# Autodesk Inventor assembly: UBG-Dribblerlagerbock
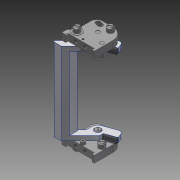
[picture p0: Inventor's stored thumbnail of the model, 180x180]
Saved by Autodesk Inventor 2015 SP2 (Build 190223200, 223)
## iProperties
Created: 2012-07
Part Number: UBG-Dribblerlagerbock
Document SubType Name: Assembly
Designer: rYan
Mass: 50.5394 g
Surface Area: 78.4637 cm^2
Volume: 8.51648 cm^3
Density: 5.9343 g/cm^3
Author: rYan
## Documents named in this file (8)
- D:\TIGERs GIT\Hardware\mechanik\2016\Inventor\Dribbling Device\UBG-Dribblerlagerbock.iam
- D:\TIGERs GIT\Hardware\mechanik\2016\Inventor\Dribbling Device\Chipperstuetze.ipt
- D:\TIGERs GIT\Hardware\mechanik\2016\Inventor\Inhaltscenter\de-DE\DIN 927\DIN 927 - M4 x 4-14H.ipt
- D:\TIGERs GIT\Hardware\mechanik\2016\Inventor\Kicker\Chip\Chipperschwinge.ipt
- D:\TIGERs GIT\Hardware\mechanik\2016\Inventor\Inhaltscenter\de-DE\DIN 988(2)\DIN 988 - 4 x 8 x 0,3.ipt
- D:\TIGERs GIT\Hardware\mechanik\2016\Inventor\Inhaltscenter\de-DE\DIN 927\DIN 927 - M4 x 5-14H.ipt
- D:\TIGERs GIT\Hardware\mechanik\2016\Inventor\Inhaltscenter\de-DE\ISO 4762(1)\ISO 4762 - M2 x 5DIN EN ISO.ipt
- D:\TIGERs GIT\Hardware\mechanik\2016\Inventor\Kaufteile\Gelpad 10x4.ipt
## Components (19 placed, 7 different names)
1. Chipperstütze:1 — Fluchtend:1, Fluchtend:2, Passend:48, Einfügen:2, Einfügen:4, Einfügen:6, Einfügen:8, Einfügen:9
2. Chipperstütze:2 — Fluchtend:1, Fluchtend:2, Passend:49, Winkel:1, Einfügen:1, Einfügen:3, Einfügen:5, Einfügen:7, Einfügen:10
3. DIN 927 M4 x 4-14H:2 — Passend:54
4. DIN 927 M4 x 4-14H:3 — Passend:53
5. DIN 927 M4 x 5-14H:1 — Passend:55
6. DIN 927 M4 x 5-14H:2 — Passend:50, Passend:56
7. Chipperschwinge:1 — Passend:48, Passend:49, Passend:50, Winkel:1, Passend:57, Fluchtend:3, Fluchtend:4, Passend:58, Fluchtend:5, Fluchtend:6
8. DIN 988 4 x 8 x 0,3:1 — Einfügen:1, Passend:53
9. DIN 988 4 x 8 x 0,3:2 — Einfügen:2, Passend:54
10. DIN 988 4 x 8 x 0,3:3 — Einfügen:4, Passend:55
11. DIN 988 4 x 8 x 0,3:4 — Einfügen:3, Passend:56
12. DIN EN ISO 4762 M2 x 5:1 — Einfügen:5
13. DIN EN ISO 4762 M2 x 5:2 — Einfügen:6
14. DIN 927 M4 x 4-14H:4 — Einfügen:7
15. DIN 927 M4 x 4-14H:5 — Einfügen:8
16. DIN 927 M4 x 4-14H:6 — Einfügen:9
17. Gelpad 10x4:1 — Passend:57, Fluchtend:3, Fluchtend:4
18. Gelpad 10x4:2 — Passend:58, Fluchtend:5, Fluchtend:6
19. DIN 927 M4 x 4-14H:7 — Einfügen:10
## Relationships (26: Insert 10, Mate 9, Flush 6, Angle 1)
- Fluchtend:1 [Flush]: Chipperstütze:1 ↔ Chipperstütze:2
- Fluchtend:2 [Flush]: Chipperstütze:1 ↔ Chipperstütze:2
- Passend:48 [Mate]: Chipperstütze:1 ↔ Chipperschwinge:1
- Passend:49 [Mate]: Chipperstütze:2 ↔ Chipperschwinge:1
- Passend:50 [Mate]: DIN 927 M4 x 5-14H:2 ↔ Chipperschwinge:1
- Winkel:1 [Angle]: Chipperstütze:2 ↔ Chipperschwinge:1
- Einfügen:1 [Insert]: Chipperstütze:2 ↔ DIN 988 4 x 8 x 0,3:1
- Passend:53 [Mate]: DIN 927 M4 x 4-14H:3 ↔ DIN 988 4 x 8 x 0,3:1
- Einfügen:2 [Insert]: Chipperstütze:1 ↔ DIN 988 4 x 8 x 0,3:2
- Passend:54 [Mate]: DIN 927 M4 x 4-14H:2 ↔ DIN 988 4 x 8 x 0,3:2
- Einfügen:3 [Insert]: Chipperstütze:2 ↔ DIN 988 4 x 8 x 0,3:4
- Einfügen:4 [Insert]: Chipperstütze:1 ↔ DIN 988 4 x 8 x 0,3:3
- Passend:55 [Mate]: DIN 927 M4 x 5-14H:1 ↔ DIN 988 4 x 8 x 0,3:3
- Passend:56 [Mate]: DIN 927 M4 x 5-14H:2 ↔ DIN 988 4 x 8 x 0,3:4
- Einfügen:5 [Insert]: Chipperstütze:2 ↔ DIN EN ISO 4762 M2 x 5:1
- Einfügen:6 [Insert]: Chipperstütze:1 ↔ DIN EN ISO 4762 M2 x 5:2
- Einfügen:7 [Insert]: Chipperstütze:2 ↔ DIN 927 M4 x 4-14H:4
- Einfügen:8 [Insert]: Chipperstütze:1 ↔ DIN 927 M4 x 4-14H:5
- Einfügen:9 [Insert]: Chipperstütze:1 ↔ DIN 927 M4 x 4-14H:6
- Passend:57 [Mate]: Chipperschwinge:1 ↔ Gelpad 10x4:1
- Fluchtend:3 [Flush]: Chipperschwinge:1 ↔ Gelpad 10x4:1
- Fluchtend:4 [Flush]: Chipperschwinge:1 ↔ Gelpad 10x4:1
- Passend:58 [Mate]: Chipperschwinge:1 ↔ Gelpad 10x4:2
- Fluchtend:5 [Flush]: Chipperschwinge:1 ↔ Gelpad 10x4:2
- Fluchtend:6 [Flush]: Chipperschwinge:1 ↔ Gelpad 10x4:2
- Einfügen:10 [Insert]: Chipperstütze:2 ↔ DIN 927 M4 x 4-14H:7
